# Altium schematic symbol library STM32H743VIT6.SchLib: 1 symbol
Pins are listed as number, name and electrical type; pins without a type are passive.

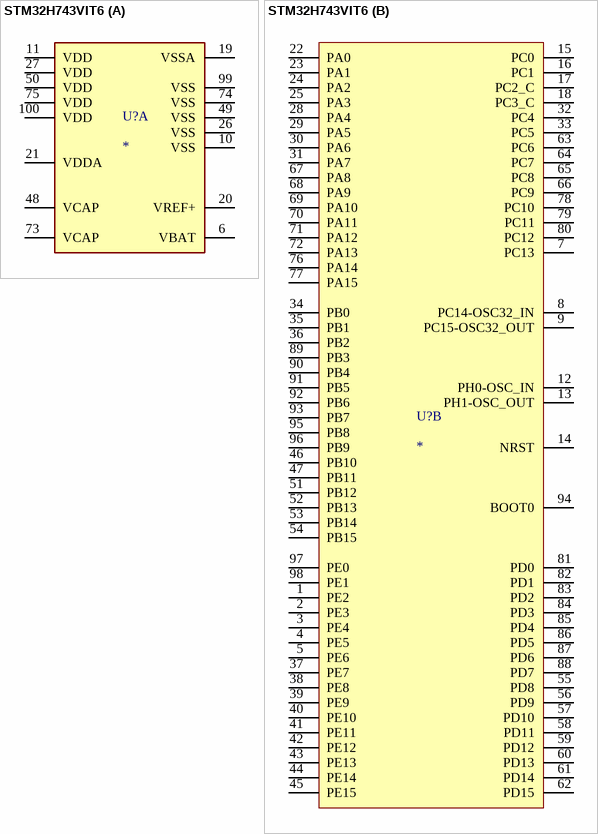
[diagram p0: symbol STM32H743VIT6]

## STM32H743VIT6
designator U?
bIG oL' dOnKEy dIcK; MF: STMicroelectronics; MP: STM32H743VIT6
footprint QFP50P1600X1600X160-100N
part A pins: 6 VBAT, 10 VSS, 11 VDD, 19 VSSA, 20 VREF+, 21 VDDA, 26 VSS, 27 VDD, 48 VCAP, 49 VSS, 50 VDD, 73 VCAP, 74 VSS, 75 VDD, 99 VSS, 100 VDD
part B pins: 1 PE2, 2 PE3, 3 PE4, 4 PE5, 5 PE6, 7 PC13, 8 PC14-OSC32_IN, 9 PC15-OSC32_OUT, 12 PH0-OSC_IN, 13 PH1-OSC_OUT, 14 NRST, 15 PC0, 16 PC1, 17 PC2_C, 18 PC3_C, 22 PA0, 23 PA1, 24 PA2, 25 PA3, 28 PA4, 29 PA5, 30 PA6, 31 PA7, 32 PC4, 33 PC5, 34 PB0, 35 PB1, 36 PB2, 37 PE7, 38 PE8, 39 PE9, 40 PE10, 41 PE11, 42 PE12, 43 PE13, 44 PE14, 45 PE15, 46 PB10, 47 PB11, 51 PB12, 52 PB13, 53 PB14, 54 PB15, 55 PD8, 56 PD9, 57 PD10, 58 PD11, 59 PD12, 60 PD13, 61 PD14, 62 PD15, 63 PC6, 64 PC7, 65 PC8, 66 PC9, 67 PA8, 68 PA9, 69 PA10, 70 PA11, 71 PA12, 72 PA13, 76 PA14, 77 PA15, 78 PC10, 79 PC11, 80 PC12, 81 PD0, 82 PD1, 83 PD2, 84 PD3, 85 PD4, 86 PD5, 87 PD6, 88 PD7, 89 PB3, 90 PB4, 91 PB5, 92 PB6, 93 PB7, 94 BOOT0, 95 PB8, 96 PB9, 97 PE0, 98 PE1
